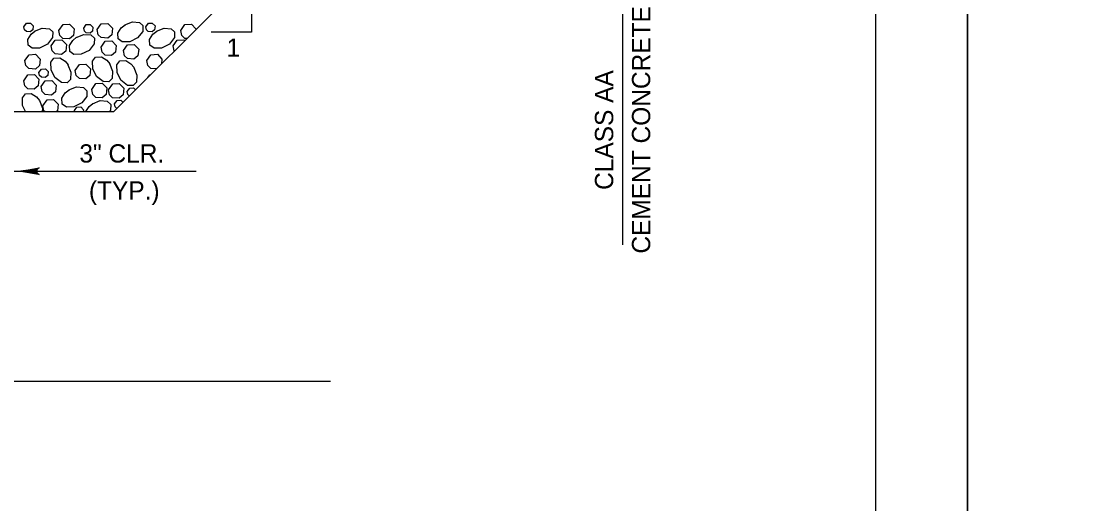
# Model space of a CAD drawing. Extents: x 636530 to 644067, y 294168 to 299122.
# Drawn here: x 639692.7 to 639869.1, y 297516.3 to 297595.3 of the extents above; entities that cross this region are included whole.
import ezdxf

# ---------------------------------------------------------------- set-up
doc = ezdxf.new("R2010")
doc.units = 0
doc.layers.add('1', color=7, linetype='Continuous')
doc.layers.add('PLT-BNDY', color=7, linetype='Continuous')

msp = doc.modelspace()

# ---------------------------------------------------------------- linework, layer by layer
at = {"layer": '1'}
for p, q in [((639832.78, 297153.48), (639832.78, 297717.48)), ((639707.8, 297580.54), (639758.59, 297631.33)), ((639791.3, 297558.7), (639791.3, 297610.58)), ((639730.37, 297600.15), (639730.37, 297593.56)), ((639730.37, 297593.56), (639723.78, 297593.56)), ((639524.92, 297580.54), (639707.8, 297580.54)), ((639677.24, 297570.78), (639721.3, 297570.78)), ((639493.7, 297536.34), (639743.33, 297536.34))]:
    msp.add_line(p, q, dxfattribs=at)
for points in [[(639693.06, 297594.45), (639693.47, 297595.03), (639694.11, 297595.06), (639694.56, 297594.6), (639694.49, 297593.95), (639694.1, 297593.62), (639693.46, 297593.66), (639693.16, 297593.95), (639693.06, 297594.45)], [(639694.81, 297593.72), (639696.06, 297594.21), (639697.22, 297594.11), (639697.77, 297593.59), (639697.75, 297592.66), (639696.92, 297591.59), (639695.63, 297590.95), (639694.42, 297590.92), (639693.73, 297591.41), (639693.67, 297592.38), (639694.22, 297593.24), (639694.86, 297593.75)], [(639698.79, 297593.84), (639699.46, 297594.79), (639700.53, 297594.86), (639701.28, 297594.08), (639701.17, 297593), (639700.51, 297592.45), (639699.45, 297592.52), (639698.95, 297593.01), (639698.79, 297593.84)], [(639702.87, 297594.23), (639703.27, 297594.81), (639703.92, 297594.84), (639704.36, 297594.38), (639704.3, 297593.73), (639703.9, 297593.4), (639703.26, 297593.44), (639702.97, 297593.73), (639702.87, 297594.23)], [(639705.07, 297593.98), (639705.74, 297594.94), (639706.82, 297595), (639707.56, 297594.23), (639707.45, 297593.14), (639706.79, 297592.59), (639705.73, 297592.67), (639705.23, 297593.15), (639705.07, 297593.98)], [(639709.58, 297594.75), (639710.84, 297595.25), (639712, 297595.15), (639712.54, 297594.63), (639712.53, 297593.69), (639711.69, 297592.62), (639710.41, 297591.98), (639709.19, 297591.96), (639708.51, 297592.44), (639708.44, 297593.41), (639709, 297594.27), (639709.63, 297594.78)], [(639713.05, 297594.45), (639713.46, 297595.03), (639714.1, 297595.06), (639714.55, 297594.6), (639714.48, 297593.95), (639714.08, 297593.62), (639713.45, 297593.66), (639713.15, 297593.95), (639713.05, 297594.45)], [(639714.79, 297593.72), (639716.05, 297594.21), (639717.21, 297594.11), (639717.76, 297593.59), (639717.74, 297592.66), (639716.91, 297591.59), (639715.62, 297590.95), (639714.4, 297590.92), (639713.72, 297591.41), (639713.66, 297592.38), (639714.21, 297593.24), (639714.85, 297593.75)], [(639718.78, 297593.84), (639719.45, 297594.79), (639720.52, 297594.86), (639721.27, 297594.08), (639721.26, 297594)], [(639719.76, 297592.5), (639719.44, 297592.52), (639718.94, 297593.01), (639718.78, 297593.84)], [(639697.52, 297591.31), (639698.2, 297592.26), (639699.27, 297592.33), (639700.02, 297591.55), (639699.91, 297590.47), (639699.24, 297589.92), (639698.18, 297589.99), (639697.69, 297590.48), (639697.52, 297591.31)], [(639701.64, 297592.7), (639702.9, 297593.2), (639704.05, 297593.1), (639704.6, 297592.58), (639704.58, 297591.64), (639703.75, 297590.57), (639702.46, 297589.93), (639701.25, 297589.91), (639700.56, 297590.39), (639700.5, 297591.36), (639701.05, 297592.22), (639701.69, 297592.73)], [(639705.7, 297591.12), (639706.38, 297592.08), (639707.45, 297592.14), (639708.2, 297591.36), (639708.09, 297590.28), (639707.42, 297589.73), (639706.36, 297589.81), (639705.87, 297590.29), (639705.7, 297591.12)], [(639717.51, 297591.31), (639718.18, 297592.26), (639719.26, 297592.33), (639719.42, 297592.16)], [(639709.38, 297590.54), (639710.05, 297591.49), (639711.12, 297591.55), (639711.87, 297590.78), (639711.76, 297589.7), (639711.1, 297589.14), (639710.04, 297589.22), (639709.54, 297589.7), (639709.38, 297590.53)], [(639717.71, 297590.45), (639717.67, 297590.48), (639717.51, 297591.31)], [(639693.21, 297588.91), (639693.89, 297589.87), (639694.96, 297589.93), (639695.7, 297589.15), (639695.6, 297588.07), (639694.93, 297587.52), (639693.87, 297587.59), (639693.38, 297588.08), (639693.21, 297588.91)], [(639700.27, 297588.23), (639700.77, 297586.98), (639700.67, 297585.82), (639700.15, 297585.27), (639699.21, 297585.29), (639698.14, 297586.12), (639697.5, 297587.41), (639697.48, 297588.62), (639697.96, 297589.31), (639698.93, 297589.37), (639699.8, 297588.82), (639700.3, 297588.18)], [(639707.1, 297588.4), (639707.6, 297587.14), (639707.5, 297585.98), (639706.98, 297585.43), (639706.04, 297585.45), (639704.98, 297586.29), (639704.33, 297587.57), (639704.31, 297588.79), (639704.8, 297589.47), (639705.76, 297589.53), (639706.63, 297588.98), (639707.13, 297588.35)], [(639711.09, 297587.79), (639711.59, 297586.53), (639711.49, 297585.37), (639710.97, 297584.82), (639710.03, 297584.84), (639708.96, 297585.68), (639708.32, 297586.96), (639708.3, 297588.18), (639708.78, 297588.86), (639709.75, 297588.92), (639710.61, 297588.37), (639711.12, 297587.74)], [(639713.2, 297588.91), (639713.87, 297589.87), (639714.95, 297589.93), (639715.69, 297589.15), (639715.61, 297588.35)], [(639714.79, 297587.53), (639713.86, 297587.59), (639713.36, 297588.08), (639713.2, 297588.91)], [(639695.52, 297586.95), (639695.93, 297587.52), (639696.57, 297587.56), (639697.02, 297587.1), (639696.95, 297586.45), (639696.56, 297586.11), (639695.92, 297586.16), (639695.62, 297586.45), (639695.52, 297586.95)], [(639701.48, 297587.28), (639702.15, 297588.24), (639703.22, 297588.3), (639703.97, 297587.53), (639703.86, 297586.44), (639703.2, 297585.89), (639702.14, 297585.97), (639701.64, 297586.45), (639701.48, 297587.28)], [(639693.02, 297585.59), (639693.7, 297586.54), (639694.77, 297586.61), (639695.52, 297585.83), (639695.41, 297584.75), (639694.75, 297584.2), (639693.69, 297584.27), (639693.19, 297584.76), (639693.03, 297585.59)], [(639695.87, 297584.64), (639696.54, 297585.59), (639697.61, 297585.66), (639698.36, 297584.88), (639698.25, 297583.8), (639697.59, 297583.25), (639696.53, 297583.32), (639696.03, 297583.81), (639695.87, 297584.64)], [(639704.17, 297584.16), (639704.84, 297585.12), (639705.91, 297585.18), (639706.66, 297584.41), (639706.55, 297583.32), (639705.89, 297582.77), (639704.83, 297582.85), (639704.33, 297583.33), (639704.17, 297584.16)], [(639706.93, 297584.12), (639707.61, 297585.08), (639708.68, 297585.14), (639709.43, 297584.37), (639709.32, 297583.28), (639708.65, 297582.73), (639707.59, 297582.81), (639707.1, 297583.29), (639706.93, 297584.12)], [(639713.4, 297586.14), (639713.69, 297586.54), (639713.81, 297586.55)], [(639693.33, 297580.54), (639692.82, 297581.55), (639692.8, 297582.77), (639693.29, 297583.45), (639694.25, 297583.52), (639695.12, 297582.96), (639695.63, 297582.33)], [(639700.42, 297584.08), (639701.68, 297584.58), (639702.83, 297584.48), (639703.38, 297583.95), (639703.36, 297583.02), (639702.53, 297581.95), (639701.24, 297581.31), (639700.03, 297581.29), (639699.34, 297581.77), (639699.28, 297582.74), (639699.83, 297583.6), (639700.47, 297584.11)], [(639709.99, 297583.83), (639710.4, 297584.4), (639711.04, 297584.44), (639711.36, 297584.1)], [(639710.34, 297583.08), (639710.09, 297583.33), (639709.99, 297583.83)], [(639695.59, 297582.38), (639696.09, 297581.12), (639696.04, 297580.54)], [(639696.16, 297581.49), (639696.84, 297582.45), (639697.91, 297582.51), (639698.66, 297581.74), (639698.55, 297580.65), (639698.41, 297580.54)], [(639696.46, 297580.54), (639696.33, 297580.66), (639696.16, 297581.49)], [(639703.21, 297580.54), (639703.74, 297581.36), (639704.37, 297581.86)], [(639704.32, 297581.83), (639705.58, 297582.33), (639706.73, 297582.23), (639707.28, 297581.71), (639707.26, 297580.77), (639707.08, 297580.54)], [(639707.91, 297581.81), (639708.32, 297582.38), (639708.96, 297582.42), (639709.31, 297582.05)], [(639708.3, 297581.03), (639708.01, 297581.31), (639707.91, 297581.81)], [(639701.32, 297580.71), (639701.73, 297581.28), (639702.37, 297581.32), (639702.82, 297580.85), (639702.79, 297580.54)], [(639701.36, 297580.54), (639701.32, 297580.71)], [(639692.56, 297570.78), (639695.54, 297571.34), (639695.42, 297571.26), (639695.31, 297571.18), (639695.25, 297571.08), (639695.19, 297570.98), (639695.17, 297570.88), (639695.16, 297570.78), (639695.17, 297570.68), (639695.19, 297570.58), (639695.25, 297570.48), (639695.31, 297570.38), (639695.42, 297570.3), (639695.54, 297570.22), (639692.56, 297570.78), (639695.42, 297570.3), (639695.31, 297570.38), (639692.56, 297570.78), (639695.25, 297570.48), (639695.19, 297570.58), (639692.56, 297570.78), (639695.17, 297570.68), (639695.16, 297570.78), (639692.56, 297570.78), (639695.17, 297570.88), (639695.19, 297570.98), (639692.56, 297570.78), (639695.25, 297571.08), (639695.31, 297571.18), (639692.56, 297570.78), (639695.42, 297571.26)]]:
    msp.add_lwpolyline(points, dxfattribs=at)
at = {"layer": 'PLT-BNDY'}
for points in [[(639006.78, 297732.48), (639847.78, 297732.48), (639847.78, 297138.48), (639006.78, 297138.48)], [(639847.78, 297732.48), (640688.78, 297732.48), (640688.78, 297138.48), (639847.78, 297138.48)]]:
    msp.add_lwpolyline(points, close=True, dxfattribs=at)

# ---------------------------------------------------------------- texts
at = {"layer": '1'}
for s, p in [('CEMENT CONCRETE', (639795.77, 297557.26)), ('CLASS AA', (639789.7, 297567.7))]:
    msp.add_text(s, height=3, rotation=90, dxfattribs=at).set_placement(p)
for s, p in [('1', (639726.29, 297589.52)), ('3" CLR.', (639702.15, 297572.18)), ('(TYP.)', (639703.71, 297566.11))]:
    msp.add_text(s, height=3, dxfattribs=at).set_placement(p)

doc.saveas('drawing.dxf')
